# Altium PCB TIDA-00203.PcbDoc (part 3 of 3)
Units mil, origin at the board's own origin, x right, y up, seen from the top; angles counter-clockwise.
Board outline 2000 x 3000 mil, 4 copper layers (TOP LAYER, L2_GND-PLANE, L3_PWR-PLANE, BOTTOM LAYER), stack 90 mil thick; 187 components, 138 nets, 683 pads, 415 vias.
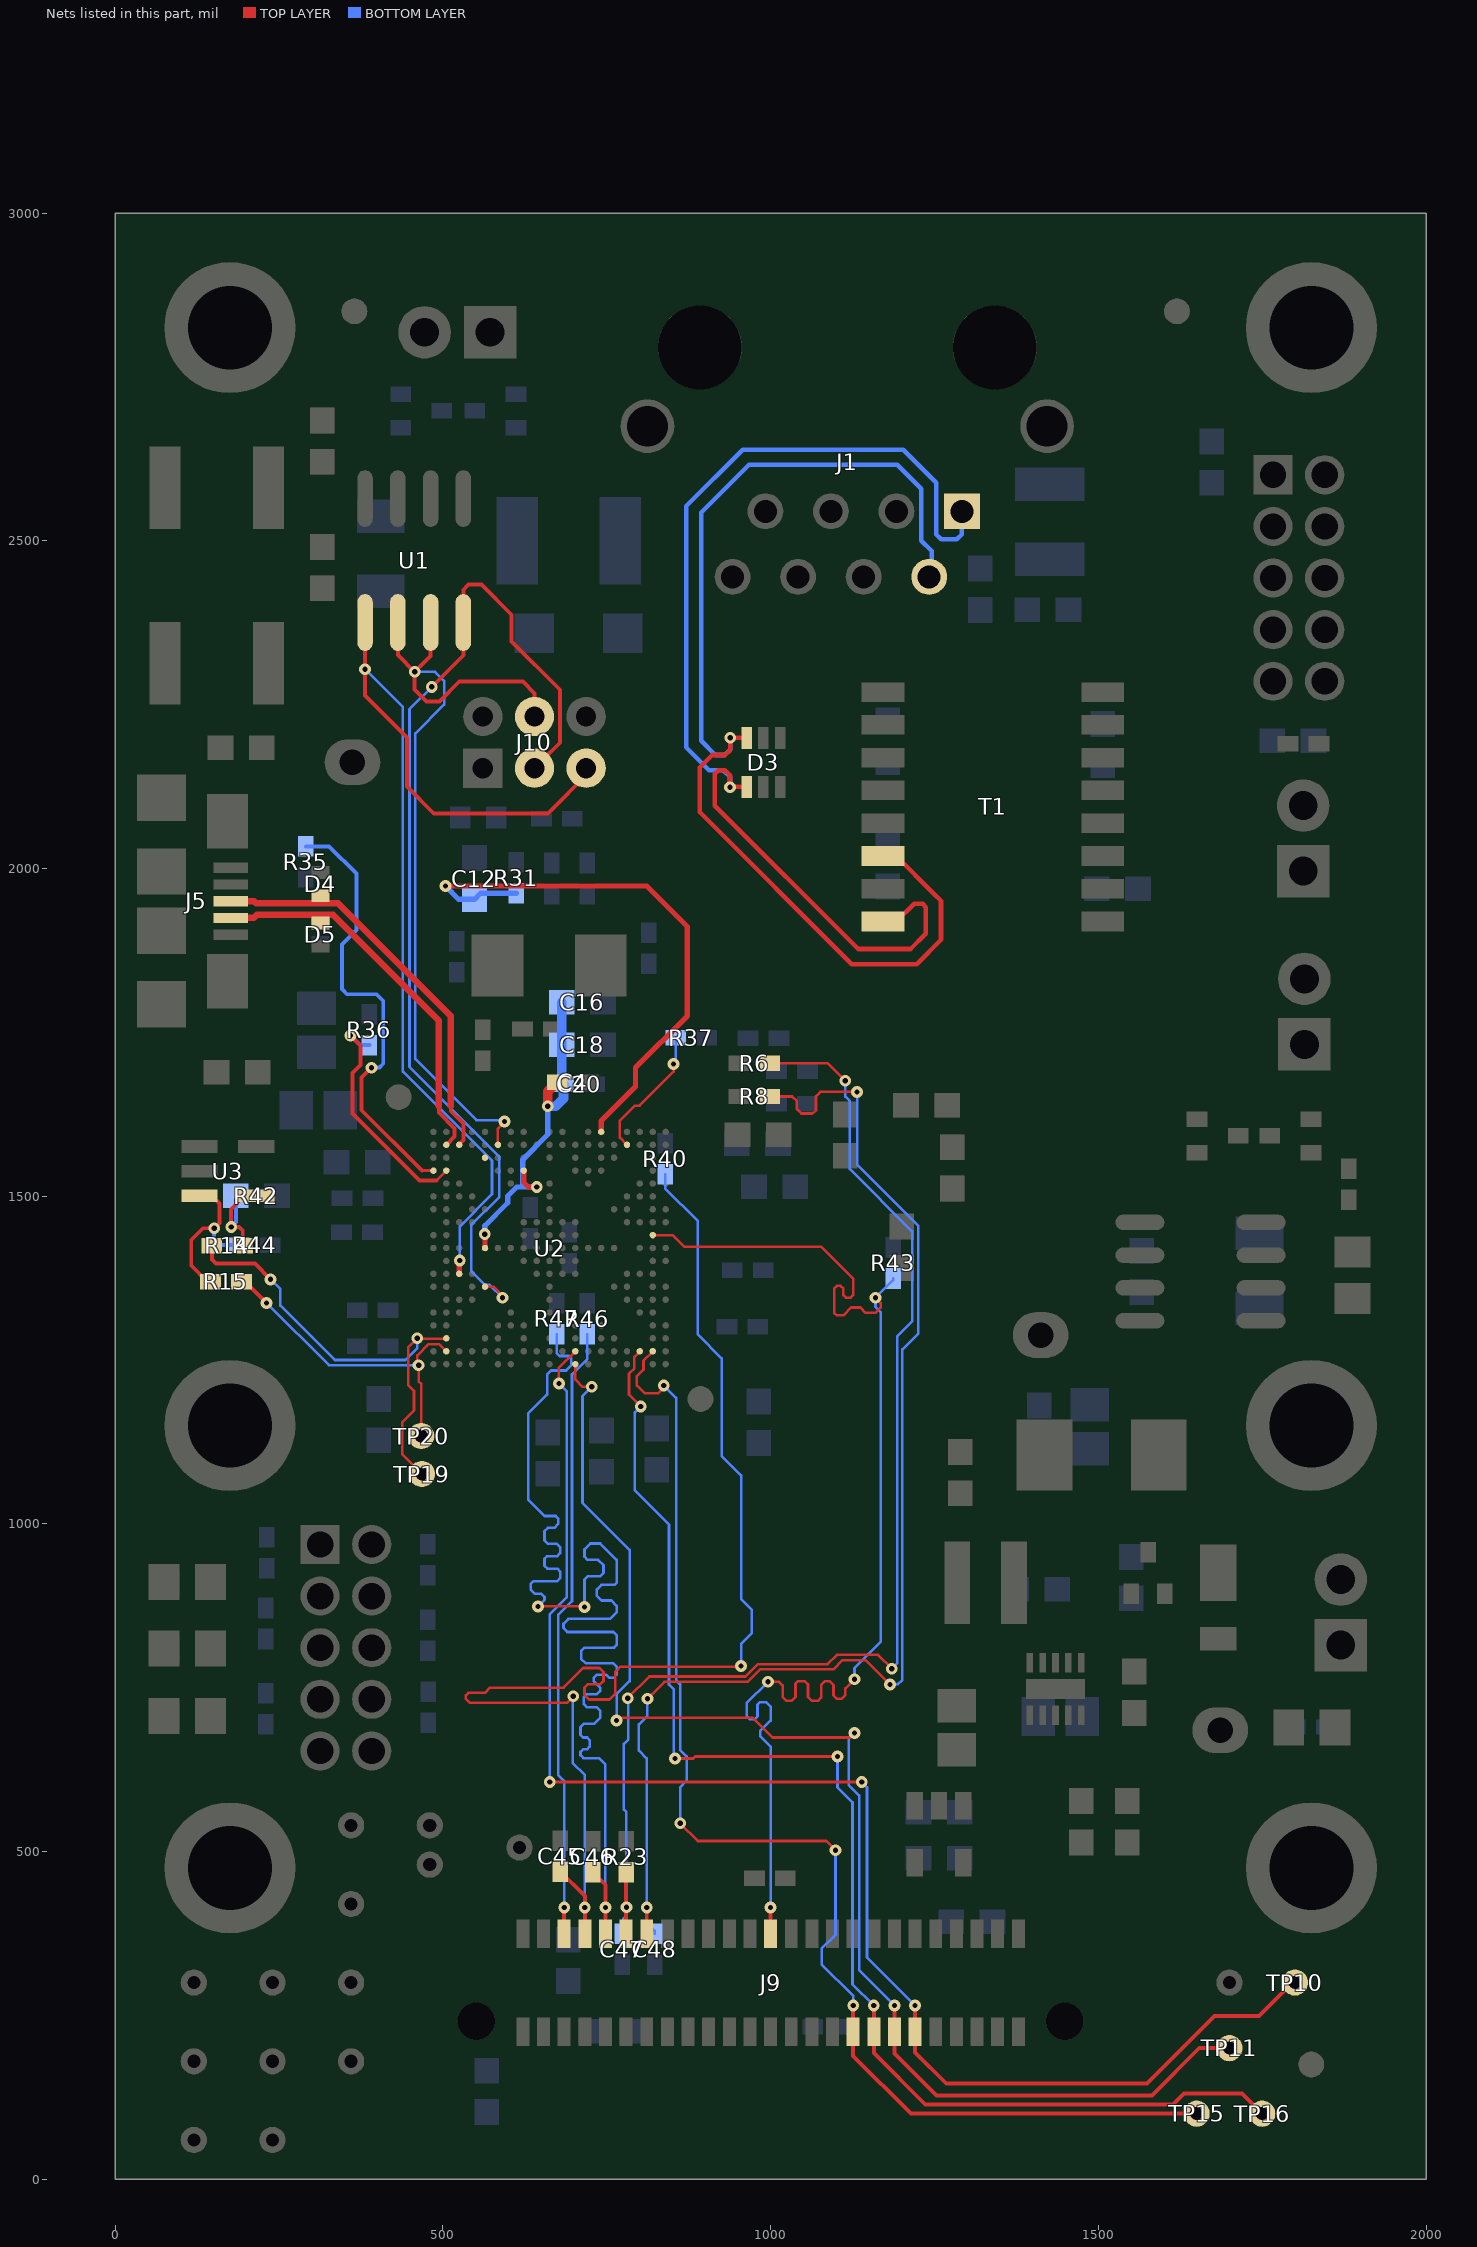
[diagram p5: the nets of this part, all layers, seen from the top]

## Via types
v1: diameter 18, hole 8, TOP LAYER to BOTTOM LAYER, tented both sides, 415 vias

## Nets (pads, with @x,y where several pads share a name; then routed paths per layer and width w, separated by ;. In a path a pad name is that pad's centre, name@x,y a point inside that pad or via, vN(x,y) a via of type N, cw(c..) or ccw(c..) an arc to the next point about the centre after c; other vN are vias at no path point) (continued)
TX+_RJ45: D3.1 J1.1 T1.16 | length 1763.3
  TOP LAYER w7: D3.1@963.41,2124.5 938.6,2124.5 v1(938,2123.91) 938,2142 930,2150 920.53,2150 915,2144.47 915,2095.53 1133.53,1877 1213.47,1877 1237,1900.53 1237,1941 1232,1946 1219,1946 1192,1919 T1.16@1171.48,1919
  BOTTOM LAYER w7: v1(938,2123.91) 938,2140 928,2150 906,2150 871,2185 871,2552.53 957.47,2639 1202.53,2639 1253,2588.53 1253,2509.53 1260.53,2502 1284,2502 1291.5,2509.5 J1.1@1291.5,2544.38 ; J1.1@1268.74,2521.62 J1.1@1291.5,2544.38 ; J1.1@1291.5,2545.38 1291.5,2544.88 J1.1@1291.5,2544.38 ; J1.1@1292,2544.88 J1.1@1291.5,2544.38
TX-_RJ45: D3.6 J1.2 T1.14 | length 1772
  TOP LAYER w7: D3.6@963.41,2199.31 v1(938.4,2199.31) 938.4,2180.4 931,2173 911,2173 892,2154 892,2086 1124,1854 1223,1854 1260,1891 1260,1950.53 1248.26,1962.26 1191.53,2019 T1.14@1171.48,2019
  BOTTOM LAYER w7: v1(938.4,2199.31) 938.4,2181.4 930,2173 915.53,2173 894,2194.53 894,2543 967,2616 1193,2616 1230,2579 1230,2500 1245.74,2484.26 1245.74,2448.62 J1.2@1242,2444.88
TX_CLK: J9.25 R43.2 U2.V11 | length 1934.4
  TOP LAYER w4: U2.V11@820.2,1440.47 850.53,1440.47 868,1423 1077,1423 1126,1374 1126,1349 1122,1345 1115,1345 1111,1349 1111,1359 1107,1363 1101,1363 1097,1359 1097,1322 1101,1318 1111,1318 1123,1330 1137,1330 1145,1322 1160,1322 1168,1330 1168,1337 v1(1160,1345) ; v1(996,759) 1013,759 1018.5,753.5 1018.5,735.5 1024,730 1032,730 1038,736 1038,756 1042,760 1052,760 1057,755 1057,736 1063,730 1072,730 1077,735 1077,754 1083,760 1090,760 1096,754 1096,738 1101,733 1108,733 1114,739 1114,749 v1(1128,763)
  TOP LAYER w6: J9.25@1000,374.8 v1(1000,414.57)
  BOTTOM LAYER w4: v1(996,759) 963.5,726.5 963.5,706.5 968,702 976,702 980,706 980,724 984,728 993,728 1000,721 1000,700 984,684 984,676 1000,660 v1(1000,414.57) ; v1(1128,763) 1128,780 1168,820 1168,1323 1160,1331 v1(1160,1345) ; v1@1163,1348 1187,1372 R43.2@1187,1374.38
TX_EN: J9.5 R46.2 | length 936.5
  TOP LAYER w6: J9.5@685.04,374.8 v1(685.04,414.57)
  BOTTOM LAYER w4: v1(685.04,414.57) 685.04,607.96 676,617 676,861 697,882 697,1228 720,1251 R46.2@720,1289.38
TXD0: C45.2 J9.7 R40.2 | length 1998.3
  TOP LAYER w4: v1(699,737) 689,727 541,727 535,733 535,738 539,742 564,742 572,750 684,750 714,780 739,780 745,774 745,760 740,755 721,755 716,750 716,739 723,732 754,732 763,741 763,774 771,782 954,782 v1(955,783)
  TOP LAYER w6: C45.2@679,469.38 716.54,431.84 v1(716.54,414.57) J9.7@716.54,374.8
  BOTTOM LAYER w4: v1(699,737) 698,736 698,635 716.54,616.46 v1(716.54,414.57) ; R40.2@839,1533.38 839,1511.79 889,1461.79 889,1289 925.38,1252.62 925.38,1103.62 955,1074 955,885 971,869 971,833 955,817 v1(955,783)
TXD1: C46.2 J9.9 R47.2 | length 1965.5
  TOP LAYER w4: v1(645,874) 715,874 v1(716,873)
  TOP LAYER w6: C46.2@729,468.38 748.03,449.35 v1(748.03,414.57) J9.9@748.03,374.8
  BOTTOM LAYER w4: v1(645,874) 655,884 655,888.5 650,893.5 640,893.5 634,899.5 634,908 638.5,912.5 674.5,912.5 679,917 679,927 674.5,931.5 659.5,931.5 655,936 655,947 658.5,950.5 674,950.5 679,955.5 679,964.5 674,969.5 660,969.5 655,974.5 655,989 660,994 670,994 676,1000 676,1008 672,1012 655,1012 630,1037 630,1168 659,1197 659,1228 665,1234 688,1234 696,1242 696,1252 692,1256 678,1256 674,1260 R47.2@674,1289.38 ; v1(716,873) 716,915 721,920 740,920 745,925 745,937 737,945 721,945 716,950 716,961 725,970 740,970 765,945 765,910 762,907 742,907 735,900 735,890 742,883 757,883 765,875 765,865 755,855 691.5,855 684,847.5 684,841 690,835 760,835 765,830 765,815 761,811 716,811 711,806 711,794 718,787 760,787 765,782 765,770 760,765 754,765 749,770 735,770 730,765 730,760 740,750 740,745 735,740 720,740 715,735 715,725 720,720 735,720 740,715 740,704 731,695 715,695 710,690 710,678 714,674 720,674 724,670 724,660 720,656 714,656 710,652 710,647 714.5,642.5 738.5,642.5 748,633 v1(748.03,414.57)
TXD2: C47.2 J9.11 R6.2 R23.1 | length 1976.5
  TOP LAYER w4: v1(782,734) 815,767 961.69,767 980.69,786 1087,786 1101,800 1164,800 v1(1185,779) ; R6.2@998.62,1703 1087,1703 v1(1114,1676)
  TOP LAYER w6: J9.11@779.53,374.8 779.53,415 R23.1@779.53,468.38
  BOTTOM LAYER w4: C47.2@775,378.62 775,397 779.63,401.63 779.63,415 v1@779.63,418 ; v1(780,415) 780,560 776,564 776,664 783,671 783,733 v1(782,734) ; v1(1114,1676) 1114,1652 1121,1645 1121,1541 1216,1446 1216,1309 1193,1286 1193,787 v1(1185,779)
TXD3: C48.2 J9.13 R8.2 | length 1967.7
  TOP LAYER w4: v1(812,733) 838,759 965,759 984,778 1096,778 1110,792 1145,792 v1(1182,755) ; R8.2@998.62,1652 1033,1652 1040,1645 1040,1633 1047,1626 1064,1626 1069,1631 1069,1652 1076,1659 v1(1132,1659)
  TOP LAYER w6: J9.13@811.02,374.8 v1(811.02,414.57)
  BOTTOM LAYER w4: v1(812,733) 812,707 799,694 799,654 811.02,641.98 v1(811.02,414.57) 811.02,390.98 823,379 C48.2@823,374.62 ; v1(1132,1659) 1132,1548 1225,1455 1225,1290 1201,1266 1201,762 1194,755 v1(1182,755)
U3CTS: U2.E17
U3RTS: J10.4 U1.2 U1.3 U2.F18 | length 1313.6
  TOP LAYER w4: U2.F18@583.98,1578.27 583.98,1602.98 594,1613 v1(594,1614)
  TOP LAYER w6: U1.2@431.22,2375.3 431.22,2325.78 v1(457,2300) ; U1.3@481.22,2375.3 481.22,2324.22 v1(457,2300) ; J10.4@650.74,2231.74 645.24,2237.24 640,2242.48 640,2267 622,2285 525,2285 495,2255 475,2255 457,2273 v1(457,2300)
  BOTTOM LAYER w4: v1(457,2300) 488,2300 502,2286 502,2250 458,2206 458,1709 551,1616 594,1616 596,1616 v1(594,1614)
U3RX: J10.5 U1.1 U2.C8 | length 1630.4
  TOP LAYER w6: U1.1@381.22,2375.3 v1(381.22,2304) 381.22,2263.78 445,2200 445,2125 486,2084 660.48,2084 723.98,2147.5 J10.5@729.48,2153
  TOP LAYER w8: U2.C8@524.92,1381.42 524.92,1400.99 v1(525.72,1401.79)
  BOTTOM LAYER w4: v1(381.22,2304) 439,2246.22 439,1690 575,1554 575,1503 525.72,1453.72 v1(525.72,1401.79)
U3TX: J10.3 U1.4 U2.E7 | length 1620.8
  TOP LAYER w4: U2.E7@564.29,1361.73 577.27,1361.73 591,1348 v1(591,1345)
  TOP LAYER w6: v1(483,2277) 531.22,2325.22 U1.4@531.22,2375.3 531.22,2425.22 539,2433 559,2433 605,2387 605,2346 679,2272 679,2192 650.74,2163.74 J10.3@650.74,2153
  BOTTOM LAYER w4: v1(483,2277) 449,2243 449,1697 586,1560 586,1499 543,1456 543,1385.67 564.02,1364.65 571.35,1364.65 v1(591,1345)
U5RX: J9.36 TP16.1 U2.U2 | length 2034.2
  TOP LAYER w4: U2.U2@800.51,1263.31 792,1254.8 792,1237 784,1229 784,1197 v1(802,1179) ; v1(854,642) 882,642 885,645 v1(1102,645)
  TOP LAYER w6: v1(1157.48,264.96) J9.36@1157.48,225.2 1157.48,192.52 1236,114 1614,114 1631,131 1719,131 TP16.1@1750,100
  BOTTOM LAYER w4: v1(802,1179) 793,1170 793,1051 845,999 845,754.75 852,747.75 852,644 v1(854,642) ; v1(1102,645) 1102,598 1125,575 1125,297.44 v1(1157.48,264.96)
U5TX: J9.34 TP15.1 U2.V2 | length 1960.5
  TOP LAYER w4: U2.V2@820.2,1263.31 806,1249.11 806,1235.21 796,1225.21 796,1211 808,1199 828,1199 837.11,1208.11 v1(837.11,1211) ; v1(862,543) 889,516 1085,516 v1(1099,502)
  TOP LAYER w6: v1(1125.98,264.96) J9.34@1125.98,225.2 1125.98,188.02 1214,100 TP15.1@1650,100
  BOTTOM LAYER w4: v1(837.11,1211) 837.11,1208.11 837,1208 837.11,1208 840,1208 856,1192 856,761 862,755 862,655.21 872,645.21 872,608 862,598 v1(862,543) ; v1(1099,502) 1099,373 1078,352 1078,328 1125.98,280.02 v1(1125.98,264.96)
U7RX: J9.40 TP10.1 U2.M2 | length 2268.7
  TOP LAYER w4: v1(663,606) v1(1139,606) ; v1(677,1214.11) 677,1238.22 U2.M2@702.09,1263.31 ; TP10.1@1796,300 TP10.1@1800,300
  TOP LAYER w6: v1(1220.47,264.96) J9.40@1220.47,225.2 1220.47,193.53 1268,146 1574,146 1677,249 1745,249 TP10.1@1796,300
  BOTTOM LAYER w4: v1(663,606) 663,862 689,888 689,1202.11 v1(677,1214.11) ; v1(1139,606) 1147,598 1147,338.43 v1(1220.47,264.96)
U7TX: J9.38 TP11.1 U2.M1 | length 2075.1
  TOP LAYER w4: U2.M1@702.09,1243.62 702.09,1219.91 713,1209 v1(727,1209) ; v1(765,700) 769,704 973,704 1003,674 1121,674 v1(1128,681)
  TOP LAYER w6: v1(1188.98,264.96) J9.38@1188.98,225.2 1188.98,192.02 1253,128 1582,128 1654,200 TP11.1@1700,200
  BOTTOM LAYER w4: v1(727,1209) 713,1195 713,1032 785,960 785,760 765,740 v1(765,700) ; v1(1128,681) 1119,672 1119,601.5 1135,585.5 1135,318.94 v1(1188.98,264.96)
USB0DM: D5.1 J5.2 U2.B18 | length 590.9
  TOP LAYER w6: 494,1637 494,1627.33 517.97,1603.36 517.97,1591 U2.B18@505.24,1578.27
  TOP LAYER w10: J5.2@176.32,1924.41 211.41,1924.41 216,1929 332.54,1929 494,1767.54 494,1637
USB0DP: D4.1 J5.3 U2.C18 | length 615.7
  TOP LAYER w6: 512,1637 512,1630 531.47,1610.53 531.47,1585.41 524.92,1578.86 U2.C18@524.92,1578.27
  TOP LAYER w10: J5.3@176.32,1950 212,1950 215,1947 340,1947 512,1775 512,1637
USB0EPEN: R14.2 TP19.1 U2.B3 | length 715.1
  TOP LAYER w4: TP19.1@468,1076 438,1106 438,1155 456,1173 456,1203 447,1212 447,1269 v1(461,1283) 461.58,1282.42 504.66,1282.42 U2.B3@505.24,1282.99
  TOP LAYER w6: R14.2@147.88,1423.5 147.88,1403.12 154,1397 213,1397 v1(237,1373)
  BOTTOM LAYER w4: v1(237,1373) 252,1358 252,1333 335,1250 443,1250 461,1268 v1(461,1283)
USB0ID: R35.2 U2.A16 | length 685.2
  TOP LAYER w4: 468,1539 485.45,1539 U2.A16@485.55,1538.9
  TOP LAYER w6: v1(391,1696) 376,1681 376,1631 468,1539
  BOTTOM LAYER w6: R35.2@291,2033.62 326.38,2033.62 368,1992 368,1906 346,1884 346,1816 354,1808 399,1808 409,1798 409,1702 403,1696 v1(391,1696)
USB0PLFT: R15.2 TP20.1 U2.B2 | length 505.5
  TOP LAYER w4: R15.2@192.62,1369 R15.2@199,1369 ; TP20.1@467,1134 467,1213.31 463,1217.31 v1(463,1242) 461,1242 461,1257 478.23,1274.23 494.31,1274.23 U2.B2@505.24,1263.31
  TOP LAYER w6: R15.2@199,1369 v1(231,1337)
  BOTTOM LAYER w4: v1(231,1337) 326,1242 v1(463,1242)
USB0VBUS: R36.2 U2.B16 | length 356.9
  TOP LAYER w4: 490.34,1524 U2.B16@505.24,1538.9
  TOP LAYER w6: v1(359,1745) 374,1730 374,1700 362,1688 362,1626 464,1524 490.34,1524
  BOTTOM LAYER w6: v1(359,1745) 373.62,1730.38 R36.2@388,1730.38
USB_EN: R14.1 R42.2 U3.4 | length 161.2
  TOP LAYER w4: U3.4@197.6,1500.6 U3.4@215.3,1500.6
  TOP LAYER w6: R14.1@194.62,1424 194.62,1447.38 189,1453 v1(177,1453) 177,1480 U3.4@197.6,1500.6
  BOTTOM LAYER w6: v1(177,1453) 184.37,1460.37 R42.2@184.37,1494
USB_PLFT: R15.1 R44.1 U3.3 | length 254.9
  TOP LAYER w4: U3.3@128.7,1500.6 U3.3@147.4,1500.6 ; R15.1@141,1369 R15.1@145.38,1369
  TOP LAYER w6: R15.1@141,1369 116,1394 116,1433 134,1451 v1(151,1451) 159,1459 159,1489 U3.3@147.4,1500.6
  BOTTOM LAYER w4: v1(151,1451) v1@151,1456
  BOTTOM LAYER w6: v1(151,1451) 151,1435.25 161,1425.25 R44.1@183.38,1425.25
VBAT: C12.1 R31.1 U2.P19 | length 882.4
  TOP LAYER w8: v1(504,1973) 811,1973 873,1911 873,1775 794,1696 794,1667 741.46,1614.46 U2.P19@741.46,1597.95
  BOTTOM LAYER w8: v1(504,1973) 524.16,1952.84 C12.1@548.21,1952.84 557.37,1962 R31.1@612,1962
VDDC_1P2V_INT: C4.1 C16.1 C18.1 C20.1 U2.E10 U2.H16 | length 543.6
  TOP LAYER w8: v1(564,1442) 564.29,1441.71 U2.E10@564.29,1420.79 ; U2.H16@623.35,1538.9 623.35,1520.65 630.21,1513.79 v1(643.22,1513.79)
  TOP LAYER w15: v1(660,1637) 660,1659.62 C4.1@674.38,1674
  BOTTOM LAYER w8: v1(564,1442) 564,1454.86 599,1489.86 599,1500 612.79,1513.79 622,1513.79 ; v1(643.22,1513.79) 622,1513.79 ; v1(660,1637) 660,1594 622,1556 622,1513.79
  BOTTOM LAYER w15: v1(660,1637) 672,1637 684.09,1649.09 C20.1@684.09,1670.79 681.22,1673.66 C18.1@681.22,1730.79 C16.1@681.22,1795.79
XOSC0: R37.2 U2.T18 | length 207.9
  TOP LAYER w4: U2.T18@780.83,1578.27 769.91,1589.19 769.91,1615.12 792.79,1638 800,1638 852,1690 v1(852,1701.5)
  BOTTOM LAYER w4: v1(852,1701.5) 855.38,1704.88 R37.2@855.38,1742
pads on no net: D3.5 FID1.1 FID2.1 FID3.1 FID4.1 FID5.1 FID6.1 H5.1 H6.1 J1.MH1 J1.MH2 J5.10 J5.11 J9.MH1 J9.MH2 LBL1.0 T1.4 T1.5 T1.12 T1.13 U2.A8 U2.A10 U2.A11 U2.A13 U2.A14 U2.A17 U2.B4 U2.B6 U2.B7 U2.B11 U2.B12 U2.B13 U2.B14 U2.B17 U2.C5 U2.C6 U2.C10 U2.C12 U2.D8 U2.D12 U2.D13 U2.E13 U2.F16 U2.FID1 U2.FID2 U2.G15 U2.G16 U2.G18 U2.G19 U2.H17 U2.H18 U2.H19 U2.J1 U2.J2 U2.J18 U2.K1 U2.K2 U2.K3 U2.K5 U2.K18 U2.K19 U2.L2 U2.L18 U2.L19 U2.M4 U2.N1 U2.N2 U2.N4 U2.N5 U2.P2 U2.P3 U2.P4 U2.R1 U2.R2 U2.R7 U2.R10 U2.R13 U2.T1 U2.T2 U2.T8 U2.T13 U2.T14 U2.T19 U2.U8 U2.U10 U2.U12 U2.V8 U2.V9 U2.V18 U2.V19 U2.W9 U2.W18 U2.W19

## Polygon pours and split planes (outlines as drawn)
NetFB1_1 on BOTTOM LAYER "BOTTOM LAYER-No Net 8" (solid, pour order 45): 660,2097 668,2089 668,2039 678,2029 678,1991 677,1990 602,1990 598,1994 598,2039 584,2053 572,2053 565,2060 565,2096 566,2097
+5V on BOTTOM LAYER "Bottom Layer-No Net 7" (solid, pour order 70): 537,125 366,125 349,108 347,106 347,84 347,70 351,66 356,61 531,61 577,61 588,72 588,100 563,125 561,125
+5V on BOTTOM LAYER "Bottom Layer-No Net 11" (solid, pour order 49): 529,125 522,118 522,70 531,61 1520,61 1643,184 1643,592 1623,612 1537,526 1485,526 1444,485 1444,360 1498,306 1498,205 1450,157 1123,157 1082,116 619,116 610,125
NetJ9_1 on BOTTOM LAYER "Bottom Layer-No Net 10" (solid, pour order 54): 658,348 610,348 600,338 600,215 582,197 549,197 537,185 537,155 551,141 597,141 630,174 657,174 666,183 666,340
NetC6_1 on BOTTOM LAYER "Bottom Layer-No Net 3" (solid, pour order 64): 1381,930 1341,930 1226,815 1226,740 1263,703 1308,703 1313,708 1324,719 1324,772 1395,843 1395,893 1395,922 1391,926 1387,930 1380,930
+5V on BOTTOM LAYER "Bottom Layer-No Net 5" (solid, pour order 57): 1380,536.78 1452.78,464 1494,464 1544,514 1579,514 1735,670 1735,966 1620,1081 1582,1081 1568,1067 1568,998 1632,934 1632,772 1608,748 1563,748 1543,728 1543,636 1516,609 1471,609 1433,647 1433,727 1426,734 1384,734 1380,730
3.3V on BOTTOM LAYER "Bottom Layer-No Net 6" (solid, pour order 44): 1373,1141 1327,1187 1283,1187 1217,1121 1217,1094 1226,1085 1517,1085 1521,1089 1521,1136 1516,1141
CHGND on BOTTOM LAYER "BOTTOM LAYER-No Net 9" (solid, pour order 43): 738,2331 746,2323 800,2323 813,2336 813,2586 926,2699 1269,2699 1362,2606 1362,2552 1370,2544 1478,2544 1489,2555 1489,2878 1561,2950 671,2950 738,2883
NetL1_1 on TOP LAYER "Top Layer-No Net 3" (solid, pour order 39): 1353,843 1361,835 1391,835 1410,816 1410,781.7 1410.6,781.1 1417.1,781.1 1420,784 1420,841 1401,860 1401,975 1391,985 1355,985 1353,983
GND on TOP LAYER "Top Layer-No Net 17" (solid, pour order 69): 662.72,1506 660,1506 657,1503 657,1478 660,1475 690,1475 703,1488 703,1496 698,1501 690,1501 685,1496 672,1496 670,1498 670,1503 667,1506 662,1506
3.3V on TOP LAYER "Top Layer-No Net 16" (solid, pour order 68): 715,1490 702,1477 702,1473 695,1466 660,1466 657,1463 657,1438 660,1435 671,1435 677,1429 677,1420 682,1415 688,1421 688,1430 693,1435 728,1435 728,1450 727,1456 727,1483 720,1490
GND on TOP LAYER "Top Layer-No Net 15" (solid, pour order 67): 666,1426 660,1426 657,1423 657,1399 660,1396 674,1396 678,1392 678,1387 676,1385 676,1384 676,1380 680,1376 721,1376 723,1376 735,1388 735,1415 724,1426 699,1426 696,1423 696,1412 692,1408 675,1408 670,1413 670,1422 667,1425 666,1426 662,1426
3.3V on TOP LAYER "Top Layer-No Net 11" (solid, pour order 65): 648,1426 639,1426 637,1424 637,1409 634,1406 620,1406 618,1404 618,1388 612,1382 606,1382 599,1375 599,1367 605,1361 626,1361 636,1351 645,1351 650,1356 667,1356 669,1358 669,1364 668,1365 668,1386 667,1387 654,1387 649,1392 649,1425
GND on TOP LAYER "Top Layer-No Net 14" (solid, pour order 66): 584,1427 580,1427 577,1424 577,1410 571,1404 571,1397 579,1389 599,1389 630,1420 630,1430 634,1434 646,1434 650,1438 650,1462 645,1467 617,1467 612,1472 609,1475 598,1475 593,1470 593,1465 593,1461 599,1455 611,1455 615,1451 618,1448 618,1440 618,1424 618,1421 606,1409 600,1409 590,1419 590,1424 587,1427 586,1427 583,1427
NetR21_2 on TOP LAYER "Top Layer-No Net 7" (solid, pour order 51): 1412,566 1422,556 1492,556 1494,558 1494,607 1431,670 1431,638 1412,619
GND on TOP LAYER "Top Layer-No Net 5" (solid, pour order 47): 1493,926 1500,919 1525,919 1536,908 1536,884 1540,880 1560,880 1562,882 1562,914 1554,922 1549,922 1534,937 1534,966.72 1528.72,972 1503,972 1493,962
GND on TOP LAYER "Bottom Layer-No Net 2" (solid, pour order 61): 1341,692 1330,681 1237,681 1231,675 1231,638 1239,630 1326,630 1342,614 1362,614 1368,620 1368,665 1358,675 1358,689 1355,692
+5V on TOP LAYER "Top Layer-No Net" (solid, pour order 37): 1651,1030 1571,1030 1551,1010 1546,1005 1546,968 1546,960 1546,940 1551,935 1616,935 1656,975 1666,985 1666,1015 1661,1020
NetD10_2 on TOP LAYER "Top Layer-No Net 2" (solid, pour order 38): 1606,910 1586,910 1581,905 1581,900 1581,895 1581,804.18 1582.2,802.98 1583.02,802.98 1606,780 1636,780 1641,785 1641,825 1641,845 1616,870 1616,905 1616,910
NetR19_2 on TOP LAYER "Top Layer-No Net 4" (solid, pour order 46): 1430,892.5 1437.5,900 1480,900 1487,907 1513,907 1521,899 1521,873 1528,866 1554,866 1560,860 1560,828 1574,814 1574,756 1572,754 1535,754 1530,759 1530,825 1499.98,855.02 1470.2,855.02 1443.18,828 1443,828 1440,825 1440,800 1437,797 1433,797 1430,800
NetR22_1 on TOP LAYER "Top Layer-No Net 8" (solid, pour order 53): 1470,722 1470,697 1470,690 1491,669 1493,667 1493,652 1493,639 1516,616 1516,565 1525,556 1572,556 1589,573 1589,609 1491,707 1491,714 1482,723 1470,723 1469,722
NetD10_2 on TOP LAYER "Bottom Layer-No Net" (solid, pour order 36): 1670,840 1730,840 1750,860 1750,951.3 1763.7,965 1925.12,965 1940,950.12 1940,894.88 1925.12,880 1925,880 1920,875 1820,875 1810,865 1810,805 1770,765 1675,765 1660,780 1660,830
NetD10_2 on TOP LAYER "Bottom Layer-No Net 1" (solid, pour order 55): 1670,840 1646,840 1641,845 1631,845 1623,837 1601,815 1601,785 1621,765 1675,765 1694,765 1691,768 1691,832 1685,838 1685,840
+5V on TOP LAYER "Bottom Layer-No Net 4" (solid, pour order 56): 1616,935 1656,895 1656,873 1660,869 1681,869 1715,869 1720,874 1720,961 1661,1020 1626,1020 1616,1010 1616,962
NetC6_1 on TOP LAYER "Top Layer-No Net 10" (solid, pour order 60): 1322,828 1328,828 1338,818 1385,818 1400,803 1400,775 1399,774 1356,774 1321,739 1308,739 1283,764 1283,802 1286,805
GND on TOP LAYER "Top Layer-No Net 6" (solid, pour order 48): 1474.1,798.1 1470,794 1470,772 1460,762 1450,762 1449,761 1380,761 1368,749 1368,719 1341,692 1341,481 1396,426 1571,426 1609,464 1609,527 1601,535 1525,535 1521,531 1521,483 1502,464 1452.78,464 1431.27,485.51 1431.27,491.73 1374,549 1374,666 1400,692 1400,733 1402,735 1477,735 1517,775 1517,823 1511,829 1497,829 1474.1,806.1
CHGND on TOP LAYER "Top Layer-No Net 13" (solid, pour order 63): 116,1830 135,1849 135,1861 143,1869 205,1869 213,1861 213,1755 174,1716 174,1654 78,1654 34,1698 34,1826 38,1830
CHGND on TOP LAYER "Top Layer-No Net 12" (solid, pour order 62): 205.5,2031.5 209.5,2035.5 209.5,2125.5 180.5,2154.5 180.5,2204.5 177.5,2207.5 46.5,2207.5 34.5,2195.5 34.5,2071.5 41.5,2064.5 113.5,2064.5 136.5,2041.5 136.5,2034.5 139.5,2031.5
NetC6_1 on TOP LAYER "Top Layer-No Net 1" (solid, pour order 58): 1252,1068 1235,1051 1235,707 1245,697 1317,697 1326,706 1326,781 1356,811 1356,817 1326,847 1308,847 1304,851 1304.14,986.14 1323,1005 1323,1061 1316,1068
3.3V on TOP LAYER "Top Layer-No Net 9" (solid, pour order 59): 1234,1089 1229,1094 1229,1133 1296,1200 1454,1200 1471,1183 1471,1056 1461,1046 1346,1046 1338,1054 1338,1070 1337,1071 1337,1072 1320,1089
CHGND on TOP LAYER "BOTTOM LAYER-No Net 9" (solid, pour order 42): 738,2331 746,2323 800,2323 813,2336 813,2586 927,2700 1269,2700 1362,2607 1362,2552 1370,2544 1478,2544 1489,2555 1489,2883 1422,2950 790,2950 738,2898
GND on L2_GND-PLANE "L2_GND-PLANE-No Net" (solid, pour order 50): 50,50 1950,50 1950,200 1950,2950 50,2950 50,50
CHGND on L2_GND-PLANE "BOTTOM LAYER-No Net 9" (solid, pour order 41): 738,2331 746,2323 800,2323 813,2336 813,2586 927,2700 1269,2700 1362,2607 1362,2552 1370,2544 1478,2544 1489,2555 1489,2883 1422,2950 790,2950 738,2898
3.3V on L3_PWR-PLANE "L3_PWR-PLANE-No Net" (solid, pour order 52): 70,2930 70,70 1930,70 1930,2930
CHGND on L3_PWR-PLANE "BOTTOM LAYER-No Net 9" (solid, pour order 40): 738,2331 746,2323 800,2323 813,2336 813,2586 927,2700 1269,2700 1362,2607 1362,2552 1370,2544 1478,2544 1489,2555 1489,2883 1422,2950 790,2950 738,2898

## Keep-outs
TOP LAYER:
  circle w10: c892,2794.88 r73.5
  circle w10: c1342,2794.88 r73.5
L2_GND-PLANE:
  circle w15: c551.18,240.94 r37
  circle w15: c1448.82,240.94 r37
  circle w10: c1825,475 r85
  circle w10: c175,475 r85
  circle w10: c892,2794.88 r73.5
  circle w10: c1342,2794.88 r73.5
  region: 715,3000.01 715,2284 817,2284 817,2046 1067,1796 1432,1796 1432,2184.08 1410,2206.08 1410,2316 1456,2362 1554,2362 1554,2998
L3_PWR-PLANE:
  circle w15: c1448.82,240.94 r37
  circle w15: c551.18,240.94 r37
  circle w10: c1825,475 r85
  circle w10: c175,475 r85
  circle w10: c892,2794.88 r73.5
  circle w10: c1342,2794.88 r73.5
  region: 715,3000.01 715,2282.08 817,2282.08 817,2046 1068.92,1794.08 1432,1794.08 1432,2184.08 1410,2206.08 1410,2316 1456,2362 1554,2362 1554,2998
BOTTOM LAYER:
  circle w10: c892,2794.88 r73.5
  circle w10: c1342,2794.88 r73.5
Keep-Out Layer:
  lines w10: -5,0 ccw(c0,0) 0,-5 ; -5,0 ccw(c0,0) 0,-5 ; -5,0 ccw(c0,0) 0,-5 ; -5,0 ccw(c0,0) 0,-5 ; -5,0 ccw(c0,0) 0,-5 ; -5,0 ccw(c0,0) 0,-5 ; -5,3450 cw(c0,3450) 0,3455 ; -5,3450 cw(c0,3450) 0,3455 ; -5,3450 cw(c0,3450) 0,3455 ; -5,3450 cw(c0,3450) 0,3455 ; -5,3450 cw(c0,3450) 0,3455 ; -5,3450 cw(c0,3450) 0,3455 ; 4950,3455 cw(c4950,3450) 4955,3450 ; 4950,3455 cw(c4950,3450) 4955,3450 ; 4950,3455 cw(c4950,3450) 4955,3450 ; 4950,3455 cw(c4950,3450) 4955,3450 ; 4950,3455 cw(c4950,3450) 4955,3450 ; 4950,3455 cw(c4950,3450) 4955,3450
  text ".Layer_Name" at 577,-858.49 h60

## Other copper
TOP LAYER:
  text ".Layer_Name" at 577,-858.49 h60
L2_GND-PLANE:
  text ".Layer_Name" at 610,-860 h60
L3_PWR-PLANE:
  region net +5V: 343.5,71 353.5,61 468.5,61 474.5,67 474.5,111 460.5,125 352.5,125 343.5,116
  text ".Layer_Name" at 640,-860 h60
BOTTOM LAYER:
  text ".Layer_Name" at 577,-858.49 h60

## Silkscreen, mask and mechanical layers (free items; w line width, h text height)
Top Overlay:
  circle w8: c775,1107.5 r63
  circle w6: c235,2671 r9.43
  circle w6: c623.06,432 r8.94
  circle w6: c960,2093 r7
  lines w6: 502.94,2042.96 592.04,2042.96 778.54,2042.96 ; 502,1956.35 502,2280.95 778,2280.95 778,1956.35 502,1956.35
  lines w8: 906.56,661.38 930.96,655.97 930.96,685.07 906.56,690.71 ; 906.63,662.36 906.63,690.42 ; 943.15,745.76 943.21,690.65 ; 943.22,654.35 943.22,682.41 ; 943.52,629.8 934.75,629.77 ; 943.48,653.71 1044.93,631.67 ; 943.56,682.24 1044.92,660.95 1044.92,631.85 ; 943.57,745.76 991.37,745.76 ; 943.6,630.64 943.59,644.32 973.52,637.26 ; 944.12,690.47 975.29,683.82 975.29,703.05 1001.79,696.29 ; 973.71,637.07 973.73,615.74 1000.75,610.54 1000.82,632.63 ; 990.31,500.2 995.19,500.2 ; 991.51,745.76 ccw(c986.92,765.47) 1006.03,758.81 ; 995.44,500.2 ccw(c995.19,536.32) 1028.19,521.63 ; 1000.82,632.69 1044.76,623.13 ; 1001.75,679 1001.79,696.29 ; 1001.75,679.25 1001.79,696.29 ; 1002,679 1050.05,669.2 ; 1006.16,759.19 1051.15,759.19 ; 1028.22,522.24 cw(c1041.23,518.58) 1038.1,531.73 1052.2,538.31 ; 1045.05,622.97 ccw(c1052.35,644.52) 1075.08,643.73 ; 1050.37,669.19 ccw(c1051.3,671.55) 1053.84,671.65 ; 1051.45,759.26 1068.3,713.99 ; 1052.3,538.46 ccw(c1040.47,562.83) 1067.05,557.57 ; 1053.67,671.46 1053.67,681.8 ; 1053.8,681.98 1074.67,676.99 ; 1054.81,598.04 ccw(c1066.93,588.01) 1056.3,576.41 ; 1055.01,597.96 1063.63,601.71 ; 1056.36,576.24 1062.53,570.54 ; 1062.7,570.44 cw(c1056.08,560.91) 1067.05,557.11 ; 1063.88,601.88 1099.89,619.31 ; 1068.16,714.01 ccw(c1113.01,731.86) 1119.14,683.99 ; 1075.07,644.32 1075.08,676.85 ; 1099.11,619.01 ccw(c1076.5,678.54) 1138.49,664 ; 1119.26,684.05 1136.56,685.41 ; 1136.91,685.38 1138.47,685.38 1138.51,667.35 ; 1138.47,681.22 1138.5,664.75 ; 893.18,566.37 893.18,629.77 ; 893.18,566.37 893.18,629.77 ; 893.18,566.37 990.36,566.37 ; 893.18,566.37 990.36,566.37 ; 893.18,629.77 934.75,629.77 ; 893.18,629.77 934.75,629.77 ; 990.36,566.37 990.36,500.37 990.36,566.37
  lines w9: 733.5,1150 817.5,1066
  text "PB" at 736,1083.5 h50
  text "EXAS" at 1015.84,829.73 h80 r90
  text "NSTRUMENTS" at 1090.84,817.23 h80 r90
  text "I" at 1091.92,795.79 h100 r90
  text "T" at 1015.84,773.48 h100 r90
  text "TIDA-00203" at 875,110 h40
  text "REV:E1" at 951,47 h40
  text ".Layer_Name" at 567,-838 h40
Bottom Overlay:
  lines w6: 31,934 31,854.22 50.02,835.2 ; 230,659 230,645 294,581 369,581 393,557 393,293.63 404.82,281.82 ; 390.18,281.82 404.82,281.82 ; 404.82,294.18 404.82,281.82 ; 1009,2156 1039,2156 1043,2152 1059,2136 1059,1960 1045,1946 787,1946 751,1910 660,1910 518,1910 505,1923 477,1951 477,2095 492,2110 680,2110 755,2110 775,2130 801,2156 1016,2156
  text ".Layer_Name" at 577,-858.49 h40
Top Paste:
  text ".Layer_Name" at 577,-858.49 h60
Bottom Paste:
  text ".Layer_Name" at 577,-858.49 h60
Top Solder:
  text "Soldermask Top" at 577,-858.49 h60
Bottom Solder:
  text "Soldermask Bottom" at 577,-858.49 h60
Drill Guide:
  text ".Layer_Name" at 577,-858.49 h60
M1 Board Outline:
  the board outline again, w6
  text ".Layer_Name" at 577,-854 h60
M2 Board Dimensions:
  rectangle: 124.5,-410.5 499.5,-285.5
  rectangle: -0.5,-285.5 124.5,-160.5
  lines w7: -0.5,-285.5 999.5,-285.5 ; 124.5,-410.5 124.5,-160.5 ; 249.5,-410.5 249.5,-160.5 ; 499.5,-410.5 499.5,-160.5 ; 749.5,-410.5 749.5,-160.5 ; -0.5,-410.5 -0.5,-160.5 999.5,-160.5 999.5,-410.5 -0.5,-410.5
  lines w10: -0.5,-475.5 -0.5,-455.5 ; 59.5,-485.5 -0.5,-465.5 ; 59.5,-445.5 -0.5,-465.5 ; 223.58,-465.5 -0.5,-465.5 ; 775.42,-465.5 999.5,-465.5 ; 939.5,-485.5 999.5,-465.5 ; 939.5,-445.5 999.5,-465.5 ; 999.5,-475.5 999.5,-455.5
  text "1000 (mil)" at 233.58,-501.49 h60
M3 3D STEP Top:
  text ".Layer_Name" at 577,-858.49 h60
M4 3D STEP Bottom:
  text ".Layer_Name" at 577,-858.49 h60
M5 Assembly Top:
  circle w10: c222,2612 r13.6
  circle w6: c617.38,506 r20.62
  lines w6: 36.89,2321.02 273.11,2321.02 273.11,2572.98 36.89,2572.98 36.89,2321.02
  lines w10: -292,-930.17 6308,-930.17 ; -292,-726.83 6310,-726.83 ; -292,-523.5 -292,-1133.5 3713,-1133.5 6310,-1133.5 6310,-523.5 -291.5,-523.5 -291.5,-1133.5 1284,-1133.5 ; 2173,-1133.5 2173,-523.5 ; 3735,-726 3735,-522.67 ; 4280,-726.83 4280,-523.5 ; 5284,-1133 5284,-930.17
  text "SW1" at 114,2422 h40
  text "TP3" at 633,537 h40 r90
  text "TIDA-00226 (ISE5001)" at 695,115 h40
  text "REV:E1" at 951,47 h40
  text "COMPONENTS MARKED 'DNP' SHOULD NOT BE POPULATED." at 1153.5,-318.5 h60
  text "ASSEMBLY VARIANT:" at 1153,-434 h60
  text ".VariantName" at 2189,-434 h60
  text "TIDA-00203" at 2807,-651.67 h60
  text "REV:" at 3852,-653 h60
  text "E1" at 4079,-653 h60
  text "PCB VIEWED FROM TOP SIDE" at -228.5,-655.67 h60
  text "BOARD #:" at 2248,-655.67 h60
  text "SVN REV:" at 4476,-655.67 h60
  text ".VersionControl_RevNumber" at 4982,-655.67 h60
  text "CAN-to-Ethernet Converter" at 2240,-855 h60
  text "ASSEMBLY TOP" at 565,-857 h60
  text "LAYER NAME =" at -228.5,-858.49 h60
  text ".plot_File_Name" at 395,-1057 h60
  text "GENERATED    :" at 3056.5,-1060 h60
  text ".Print_Date" at 3926,-1060 h60
  text ".Print_Time" at 4655,-1060 h60
  text "TEXAS INSTRUMENTS" at 5301,-1060 h60
  text "PLOT NAME=" at -228.5,-1064.34 h60
M6 Assembly Bottom:
  lines w6: 469,1950 506,1913 744,1913 785,1954 1017,1954 1032,1969 1032,2129 1032,2146 1011,2167 953,2167 658.25,2167 541,2167 469,2095 469,1950 ; 620,2330 793,2330 793,2387 620,2387 620,2330
  lines w10: -292.5,-727.33 6309.5,-727.33 ; -290.5,-930.67 6309.5,-930.67 ; 736.5,-1134.5 736.5,-931.67 ; 1737.5,-727.33 1737.5,-524 ; 2236,-723 2236,-519.67 ; 3844.5,-1134 3844.5,-524 ; 4733.5,-1134 6309,-1134 6309,-524 -292.5,-524 -292.5,-1134 2304.5,-1134 6309.5,-1134 6309.5,-524
  text "R28" at 923,2340 h40
  text "TIDA-00226 (ISE5001)" at 1522,81 h40
  text "REV:E1" at 1179,23 h40
  text "COMPONENTS MARKED 'DNP' SHOULD NOT BE POPULATED." at 6102,-318 h60
  text ".VariantName" at 5058,-434 h60
  text "ASSEMBLY VARIANT:" at 6097,-434 h60
  text ".VersionControl_RevNumber" at 1035.5,-656.17 h60
  text "SVN REV:" at 1541.5,-656.17 h60
  text "BOARD #:" at 3769.5,-656.17 h60
  text "PCB VIEWED FROM BOTTOM SIDE" at 6246,-656.17 h60
  text "REV:" at 2181,-664 h60
  text "E1" at 1868,-666 h60
  text "TIDA-00203" at 3264,-666 h60
  text "CAN-to-Ethernet Converter" at 3770,-857 h60
  text "LAYER NAME =" at 6209,-857 h60
  text "ASSEMBLY BOTTOM" at 5424,-862 h60
  text ".plot_File_Name" at 5641,-1063 h60
  text ".Print_Time" at 1364,-1064 h60
  text ".Print_Date" at 2093,-1064 h60
  text "GENERATED:" at 2962.5,-1064 h60
  text "PLOT NAME=" at 6246,-1064.84 h60
  text "TEXAS INSTRUMENTS" at 715,-1068 h60
M9 Title Sheet:
  drawing of 57 lines, arcs and shapes, not listed
  text "1" at 739.84,8036.5 h70
  text "2" at 3235.5,8036.5 h70
  text "3" at 5724.84,8036.5 h70
  text "4" at 8231.51,8036.5 h70
  text "5" at 10730.5,8036.5 h70
  text "6" at 13235.5,8036.5 h70
  text "A" at -416.5,6893.5 h70
  text "A" at 14383.5,6893.5 h70
  text "B" at -416.5,4513.5 h70
  text "B" at 14383.5,4513.5 h70
  text "C" at -416.5,2138.5 h70
  text "C" at 14383.5,2138.5 h70
  text "PROJECT TITLE:" at 11343.5,277.5 h45
  text ".PRJ_Title" at 11393.5,144.17 h70
  text "DESIGNED FOR:" at 11343.5,-23.5 h45
  text ".PRJ_Customer" at 11393.5,-163.5 h70
  text "D" at -416.5,-231.5 h70
  text "D" at 14383.5,-231.5 h70
  text "FILE NAME:" at 11343.5,-323.5 h45
  text ".Pcb_File_Name_No_Path" at 11393.5,-443.5 h70
  text "Texas Instruments (TI) and/or its licensors do not warrant the accuracy or completeness of this specification" at 6374,-605.34 h45
  text "ENGINEER:" at 11343.5,-613.5 h45
  text "LAYOUT BY:" at 12848.5,-613.5 h45
  text "or any information contained therein. TI and/or its licensors do not warrant that this design will meet" at 6329.01,-718 h45
  text ".PRJ_Engineer" at 11393.5,-768.49 h70
  text "the specifications, will be suitable for your application or fit for any particular purpose, or will operate in" at 6329.01,-830.67 h45
  text "ALTIUM DESIGNER VERSION:" at 12848.5,-923.5 h45
  text "an implementation. TI and/or its licensors do not warrant that the design is production worthy. You should" at 6329.01,-943.33 h45
  text "completely validate and test your design implementation to confirm the system functionality for your application." at 6374,-1056 h45
  text ".print_Scale" at 11393.5,-1056.83 h70
  text ".Application_BuildNumber" at 12899,-1056.83 h70
  text "1" at 739.84,-1263.5 h70
  text "2" at 3235.5,-1263.5 h70
  text "3" at 5724.84,-1263.5 h70
  text "4" at 8231.51,-1263.5 h70
  text "5" at 10730.5,-1263.5 h70
  text "6" at 13235.5,-1263.5 h70
M10 Fab Notes:
  drawing of 235 lines, arcs and shapes, not listed
  text "DESIGN INFORMATION" at 12381.02,6810 h60
  text "IMPEDANCE TABLE" at 7350,6800 h60
  text "SPACING" at 8652,6651 h60
  text "TRACE WIDTH" at 7800,6650 h60
  text "REFERENCE LAYER" at 10100,6650 h60
  text "IMPEDANCE" at 9293,6649 h60
  text "(REFER ALSO ARRAY/PANEL PROFILING INFORMATION)" at 12019.46,6648.29 h60
  text "LAYER" at 7201,6644 h60
  text "BOARD SIZE" at 11333.46,6644 h60
  text "2000MIL" at 11795.78,6516.18 h60
  text "X" at 12301.46,6516.18 h60
  text "3000MIL" at 12532.78,6516.18 h60
  text "10 MIL" at 8000,6450 h60
  text "8 MIL" at 8719,6450 h60
  text "TOP" at 7248,6449 h60
  text "90 OHM +/-10%" at 9177,6448 h60
  text "L2_GND-PLANE" at 10177,6448 h60
  text "Number of Layers :" at 11736.46,6319 h60
  text "4" at 12831.27,6309 h60
  text "L2_GND-PLANE" at 10180,6255 h60
  text "TOP" at 7240,6254 h60
  text "7 MIL" at 8000,6250 h60
  text "16 MIL" at 8694,6250 h60
  text "100 OHM +/-10%" at 9160,6248 h60
  text "MIN. TRACK WIDTH:" at 11736.46,6180 h60
  text "4" at 12832.7,6180 h60
  text "MIL" at 12987.46,6180 h60
  text "100 OHM +/-10%" at 9157,6066 h60
  text "16 MIL" at 8700,6062 h60
  text "7 MIL" at 8008,6061 h60
  text "L3_PWR-PLANE" at 10181,6061 h60
  text "BOTTOM" at 7232,6053 h60
  text "MIN. CLEARANCE:" at 11736.46,6048 h60
  text "MIL" at 12987.46,6048 h60
  text "4" at 12828,6046 h60
  text "MIN. VIA PAD SIZE:" at 11736.46,5916 h60
  text "18" at 12802.71,5916 h60
  text "MIL" at 12987.46,5916 h60
  text "0.127mm (5MIL)" at 12431.46,5774.29 h60
  text "EXTERNAL" at 13182,5772 h60
  text "MINIMUM ANNULAR RING" at 11407.23,5770 h60
  text "PER" at 11607.23,5652 h60
  text "IPC-D-275 CLASS 2 LEVEL C" at 11827.23,5652 h60
  text "MIL, HOLES" at 13315.46,5539.71 h60
  text "+/-" at 12923,5539 h60
  text "+/-" at 13777,5539 h60
  text "REGISTRATION TOLERANCES:" at 11407.23,5534 h60
  text "METAL" at 12607,5534 h60
  text "5" at 13183.2,5534 h60
  text "3" at 14016.2,5534 h60
  text "MIL" at 14132.46,5534 h60
  text "MATERIAL:" at 11332.46,5324.54 h60
  text "FR-4 High Tg" at 12318.9,5184.21 h60
  text "FR-408" at 11753.46,5175.64 h60
  text "X" at 12165.46,5175.64 h60
  text "OTHER" at 13241.46,5175.64 h60
  text "63 MIL (1.6mm) +/-10%" at 12073.56,5012.92 h60
  text "THICKNESS:" at 11407.23,5008.64 h60
  text "X" at 11945.4,5008.64 h60
  text "OTHER" at 13358.46,5008.64 h60
  text "TOLERANCE:" at 11407.23,4850.64 h60
  text "X" at 12246.53,4850.64 h60
  text "ANSI IPC-6012 TYPE 3 CLASS 2" at 12433.48,4850.64 h60
  text "OTHER +/-" at 12433.46,4694.64 h60
  text "BOW & TWIST:" at 11407.23,4537.64 h60
  text "X" at 12246.53,4537.64 h60
  text "ANSI IPC-6012 TYPE 3 CLASS 2" at 12433.48,4537.64 h60
  text "OTHER +/-" at 12433.46,4379.13 h60
  text "COPPER THICKNESS (FINISHED):" at 11332.46,4243.64 h60
  text "1.4MIL (1oz)" at 12212.46,4090.92 h60
  text "2MIL (1.4oz)" at 12979.46,4090.92 h60
  text "2.8MIL (2oz)" at 13706.46,4090.92 h60
  text "OUTER:" at 11689.46,4086.64 h60
  text "X" at 12084,4086 h60
  text "1.4MIL (1oz)" at 12212.46,3933.92 h60
  text "2.8MIL (2oz)" at 12979.46,3933.92 h60
  text "N/A" at 13706,3934.29 h60
  text "INNER SIGNAL:" at 11400.38,3929.64 h60
  text "X" at 12085.42,3929.64 h60
  text "DRILLING:" at 11332.46,3790.64 h60
  text "REFERENCE:" at 11407.23,3673.64 h60
  text "X" at 12055.46,3673.64 h60
  text "AS SHOWN" at 12242.46,3673.64 h60
  text "X" at 12956.46,3673.64 h60
  text "NC_DRILL FILES" at 13093.46,3673.64 h60
  text "PTH MIN COPPER THICKNESS:" at 11407.23,3515.64 h60
  text "X" at 12757.46,3515.64 h60
  text "1MIL" at 12894.46,3515.64 h60
  text "OTHER" at 13391.46,3515.64 h60
  text "BOARD FINISH:" at 11332.46,3356.64 h60
  text "SILKSCREEN:" at 11487.68,3238.64 h60
  text "X" at 12436.46,3238.64 h60
  text "TOP" at 12562.46,3238.64 h60
  text "X" at 12946.46,3238.64 h60
  text "BOTTOM" at 13073.46,3238.64 h60
  text "SILKSCREEN COLOR:" at 11486.01,3072.64 h60
  text "X" at 12433.75,3072.64 h60
  text "WHITE" at 12560.79,3072.64 h60
  text "OTHER" at 13071.79,3072.64 h60
  text "SOLDER RESIST COLOR:" at 11592.01,2921.64 h60
  text "GREEN" at 12286.79,2762.44 h60
  text "X" at 12049,2750 h60
  text "BLUE" at 12857,2744 h60
  text "OTHER" at 13306,2740 h60
  text "IMMERSION GOLD (ENIG)" at 12393.46,2553.92 h60
  text "ENEPIG" at 13731,2550.64 h60
  text "SURFACE FINISH:" at 11332.46,2549.64 h60
  text "X" at 12206.51,2549.64 h60
  text "IMM. TIN/SILVER OR EQUIV" at 11662,2392.64 h60
  text "OTHER" at 13093.46,2392.64 h60
  text "ARRAY/PANEL:" at 11332.46,2213.64 h60
  text "CUT AND TRIM PER MECH LAYER 1" at 12393.46,2209.35 h60
  text "N.C. ROUTE" at 12393.46,2057.64 h60
  text "X" at 13072.46,2057.64 h60
  text "V. SCORE" at 13259.46,2057.64 h60
  text "CERTIFICATION:" at 11332.46,1920.64 h60
  text "MATERIALS AND WORKMANSHIP FOR ALL PCBS" at 12057.46,1920.64 h60
  text "TO MEET OR EXCEED THE REQUIREMENTS OF:" at 12057.46,1822.64 h60
  text "X" at 11683.96,1686.13 h60
  text "ANSI IPC-A-600F CLASS ->" at 11822.96,1686.13 h60
  text "X" at 13462.02,1686.13 h60
  text "2" at 13580.96,1686.14 h60
  text "1" at 13265.96,1684.64 h60
  text "3" at 13934.96,1684.64 h60
  text "X" at 11686.02,1526.64 h60
  text "UL 94V-0" at 11822.96,1526.64 h60
  text "X" at 12498.02,1526.64 h60
  text "RoHS" at 12634.96,1526.64 h60
  text "OTHER" at 13279.36,1526.64 h60
  text "PER ORDER" at 13676.42,1526.64 h60
  text "ADDITIONAL REQUIREMENTS:" at 11332.46,1385.64 h60
  text "X" at 13749,1298 h60
  text "VIA TENTING:" at 12807,1290 h60
  text "YES" at 13504,1289 h60
  text "NO" at 13920,1284 h60
  text "MICROSECTION:" at 11407.23,1270.64 h60
  text "YES" at 12312.96,1270.64 h60
  text "REQUIRED" at 13174.46,1114.49 h60
  text "BARE BOARD ELEC. TEST:" at 11407.23,1111.64 h60
  text "NONE" at 12712.96,1111.64 h60
  text "X" at 13047.46,1111.64 h60
  text "PER ORDER" at 13766.46,1111.64 h60
  text "MANUFACTURER'S UL:" at 11407.23,954.64 h60
  text "RAIL" at 12572.96,950.35 h60
  text "METAL" at 13064.77,950.35 h60
  text "X" at 13440,950 h60
  text "SILK" at 13576.46,950.35 h60
M11 Gerber Information:
  lines w10: -292,-930.17 6308,-930.17 ; -292,-726.83 6310,-726.83 ; -292,-523.5 -292,-1133.5 3713,-1133.5 6310,-1133.5 6310,-523.5 -291.5,-523.5 -291.5,-1133.5 1284,-1133.5 ; 2173,-929 2173,-523.5 ; 3065,-1132 3065,-933.67 ; 3690,-725 3690,-526.67 ; 4280,-726.83 4280,-523.5 ; 5273,-1132 5273,-931.17
  text "TIDA-00203" at 2807,-651.67 h60
  text "ALL ARTWORK VIEWED FROM TOP SIDE" at -228.5,-655.67 h60
  text "BOARD #:" at 2248,-655.67 h60
  text "E1" at 4024,-656 h60
  text "SVN REV:" at 4476,-655.67 h60
  text ".VersionControl_RevNumber" at 4982,-655.67 h60
  text "REV:" at 3785,-657 h60
  text "CAN-to-Ethernet Converter" at 2240,-855 h60
  text "LAYER NAME =" at -228.5,-858.49 h60
  text ".plot_File_Name" at 451,-1057 h60
  text "TEXAS INSTRUMENTS" at 5292,-1062 h60
  text "PLOT NAME =" at -228.5,-1064.34 h60
  text "GENERATED:" at 3087.5,-1064 h60
  text ".Print_Date" at 3957,-1064 h60
  text ".Print_Time" at 4686,-1064 h60
M12 Stackup:
  lines w6: 11333,7694.75 14233,7694.75 ; 11333,7811.45 14233,7811.45 ; 11273,6961 ccw(c11311,6961) 11311,6923 14255,6923 ccw(c14255,6961) 14293,6961 14293,7910 ccw(c14255,7910) 14255,7948 11311,7948 ccw(c11311,7910) 11273,7910 11273,6961
  text "Layer Stack Up Detail for: TIDA-00203.PcbDoc" at 11333,7841.12 h52
  text "Layer" at 11333,7767.95 h27
  text "Gerber" at 12349.46,7767.95 h27
  text "Copper" at 12999.23,7767.95 h27
  text "Dielectric" at 13693.1,7767.95 h27
  text "Name" at 11333,7713.95 h27
  text "Document" at 12349.46,7713.95 h27
  text "Thickness" at 12999.23,7713.95 h27
  text "Material" at 13693.1,7713.95 h27
  text "Top Solder Mask" at 11333,7638.36 h38
  text "(.GTS)" at 12349.46,7638.36 h38
  text "Solder Resist" at 13693.1,7638.36 h38
  text "TOP LAYER" at 11333,7531.59 h38
  text "(.GTL)" at 12349.46,7531.59 h38
  text "1.4mil" at 12999.23,7531.59 h38
  text "FR-4" at 13693.1,7478.21 h38
  text "L2_GND-PLANE" at 11333,7424.82 h38
  text "(.G1)" at 12349.46,7424.82 h38
  text "1.4mil" at 12999.23,7424.82 h38
  text "FR-4" at 13693.1,7371.44 h38
  text "L3_PWR-PLANE" at 11333,7318.05 h38
  text "(.G2)" at 12349.46,7318.05 h38
  text "1.4mil" at 12999.23,7318.05 h38
  text "FR-4" at 13693.1,7264.67 h38
  text "BOTTOM LAYER" at 11333,7211.28 h38
  text "(.GBL)" at 12349.46,7211.28 h38
  text "1.4mil" at 12999.23,7211.28 h38
  text "Bottom Solder Mask" at 11333,7104.51 h38
  text "(.GBS)" at 12349.46,7104.51 h38
  text "Solder Resist" at 13693.1,7104.51 h38
M13 Component Bodies Top:
  text ".Layer_Name" at 577,-858.49 h60
M14 Component Bodies Bottom:
  text ".Layer_Name" at 577,-858.49 h60
M15 Courtyards Top:
  lines w0.1: 699,3000 732,3000 ; 715,2980 715,3019 715,3000.01
  text ".Layer_Name" at 577,-858.49 h60
M16 Courtyards Bottom:
  text ".Layer_Name" at 577,-858.49 h60
Drill Drawing:
  text ".legend" at 3528,1326 h60
  text "Drill Table" at 3527,1151 h60
  text "DRILL TOLERANCE" at 3517,995 h60
  text "FOR 8MIL DRILL +0/-8MIL" at 3513,867 h60
  text ".Layer_Name" at 577,-858.49 h60

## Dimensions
175,2825 to 0,3000 on M2 Board Dimensions
1825,2825 to 2000,3000 on M2 Board Dimensions
175,2825 to 1825,2825 on M2 Board Dimensions
1825,2825 to 2000,3000 on M2 Board Dimensions
2000,3000 to 2000,0 on M2 Board Dimensions
0,3000 to 2000,3000 on M2 Board Dimensions
1825,1150 to 1825,2825 on M2 Board Dimensions
1825,475 to 1825,1150 on M2 Board Dimensions
1825,475 to 2000,0 on M2 Board Dimensions
0,0 to 0,3000 on Drill Drawing
0,3000 to 2000,3000 on Drill Drawing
